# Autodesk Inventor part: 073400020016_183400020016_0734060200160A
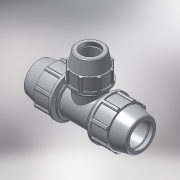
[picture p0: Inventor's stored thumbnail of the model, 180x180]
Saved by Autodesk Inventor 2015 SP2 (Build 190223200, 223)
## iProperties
Created: 2017-02
Part Number: 073400020016_183400020016_0734060200160A
Material: PVC-Piping
Description: PLASSON REDUCING TEE 20-16-20
Document SubType Name: Modeling
Designer: KIM
Mass: 92.6774 g
Surface Area: 199.44 cm^2
Volume: 66.1981 cm^3
Density: 1.4 g/cm^3
Appearance: Smooth - White
Author: Кирилл
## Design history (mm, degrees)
derived "07340.ipt"
feature "Solid1::07340.ipt"
feature "Solid2::07340.ipt"
tag "TaggingFeature1"
body "Solid1"
other parameters: "d4" = 5.70833, "d5" = 19.18, "d7" = 48, "d11" = 2.28333, "d13" = 120 deg, "d15" = 12 deg, "d16" = 41.76, "d18" = 1, "d19" = 35 deg, "d20" = 17.5 deg, "d21" = 44.64, "d23" = 0, "d25" = 360 deg, "d27" = 0.96, "d33" = 0.4, "d42" = 24.66, "d43" = 1.44, "d46" = 0.6, "d67" = 36, "d76" = 16, "d77" = 39, "d78" = 12 deg, "d80" = 120 deg, "d81" = 24, "d82" = 5.83333, "d87" = 2.33333, "d89" = 17.5, "d90" = 21, "d96" = 11.41667, "d98" = 36.27, "d99" = 35 deg, "d100" = 17.5 deg, "d102" = 0, "d103" = 0.78, "d107" = 360 deg, "d109" = 0.48, "d112" = 0.8, "d113" = 2.6, "d114" = 0, "d117" = 137, "d118" = 33.93, "d126" = 18, "d127" = 57, "d131" = 2.8, "d132" = 14.4, "d135" = 0, "d138" = 2.74, "d143" = 0, "d148" = 29.25, "d168" = 18, "d170" = 0, "d171" = 16, "d173" = 0, "d175" = 0, "d176" = 2.6, "d177" = 0, "E_" = 48, "l_" = 57, "E_1" = 39, "d_1" = 16, "H_" = 137
